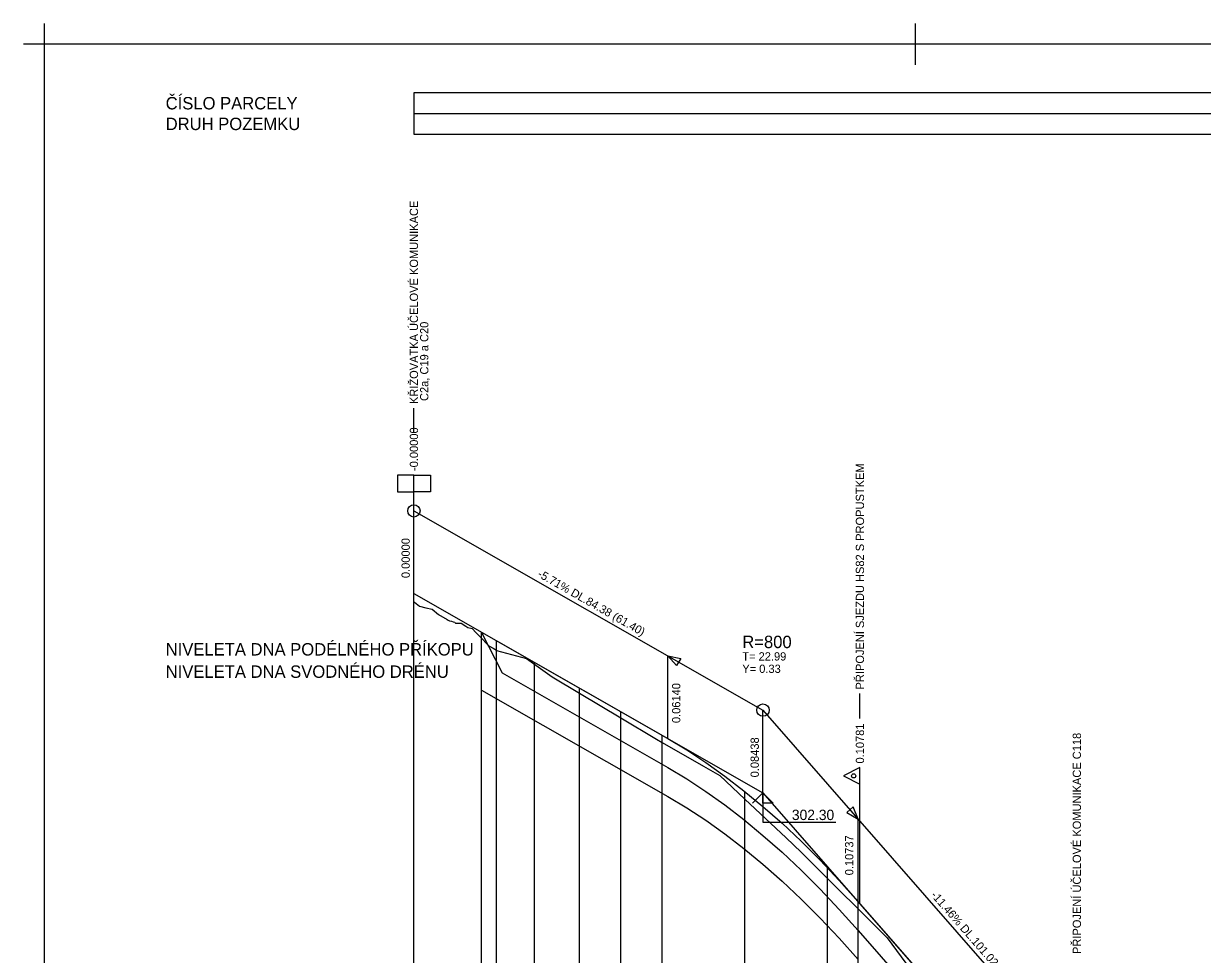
# Model space of a CAD drawing. Extents: x -24 to 1036, y -50 to 554.
# Drawn here: x -24.4 to 260.6, y 328.9 to 554 of the extents above; entities that cross this region are included whole.
import ezdxf

# ---------------------------------------------------------------- set-up
doc = ezdxf.new("R2010")
doc.units = 0
for name, color, linetype in [('KOTA', 7, 'Continuous'), ('NOVY_STAV', 7, 'Continuous'), ('NS_OBLOUK', 7, 'Continuous'), ('POPISY_NAD_TERENEM', 7, 'Continuous'), ('PRIKOPY', 7, 'Continuous'), ('REZY_PO', 7, 'Continuous'), ('SESTAVY_REZU_PO', 7, 'Continuous'), ('SVK', 7, 'Continuous'), ('SVK_STAT', 7, 'Continuous'), ('TABULKY', 7, 'Continuous'), ('ZNACKY', 7, 'Continuous')]:
    doc.layers.add(name, color=color, linetype=linetype)

msp = doc.modelspace()

# ---------------------------------------------------------------- linework, layer by layer
for p, q in [((-19.35, 554.04), (-19.35, 544.04)), ((-19.35, 554.04), (-19.35, 544.04)), ((-19.35, 554.04), (-19.35, 544.04)), ((-19.35, 554.04), (-19.35, 544.04)), ((-19.35, 554.04), (-19.35, 544.04)), ((-19.35, 554.04), (-19.35, 544.04)), ((-19.35, 554.04), (-19.35, 544.04)), ((-19.35, 554.04), (-19.35, 544.04)), ((-19.35, 554.04), (-19.35, 544.04)), ((-19.35, 554.04), (-19.35, 544.04)), ((-19.35, 554.04), (-19.35, 544.04)), ((-19.35, 554.04), (-19.35, 544.04)), ((-19.35, 554.04), (-19.35, 544.04)), ((-19.35, 554.04), (-19.35, 544.04)), ((-19.35, 554.04), (-19.35, 544.04)), ((-19.35, 554.04), (-19.35, 544.04)), ((-19.35, 554.04), (-19.35, 544.04)), ((-19.35, 554.04), (-19.35, 544.04)), ((-19.35, 554.04), (-19.35, 544.04)), ((-19.35, 554.04), (-19.35, 544.04)), ((-19.35, 554.04), (-19.35, 544.04)), ((-19.35, 554.04), (-19.35, 544.04)), ((-19.35, 554.04), (-19.35, 544.04)), ((-19.35, 554.04), (-19.35, 544.04)), ((-19.35, 554.04), (-19.35, 544.04)), ((-19.35, 554.04), (-19.35, 544.04)), ((-19.35, 554.04), (-19.35, 544.04)), ((-19.35, 554.04), (-19.35, 544.04)), ((-19.35, 554.04), (-19.35, 544.04)), ((-19.35, 554.04), (-19.35, 544.04)), ((-19.35, 554.04), (-19.35, 544.04)), ((-19.35, 554.04), (-19.35, 544.04)), ((-19.35, 554.04), (-19.35, 544.04)), ((-19.35, 554.04), (-19.35, 544.04)), ((-19.35, 554.04), (-19.35, 544.04)), ((-19.35, 554.04), (-19.35, 544.04)), ((-19.35, 554.04), (-19.35, 544.04)), ((-19.35, 554.04), (-19.35, 544.04)), ((-19.35, 554.04), (-19.35, 544.04)), ((-19.35, 554.04), (-19.35, 544.04)), ((-19.35, 554.04), (-19.35, 544.04)), ((-19.35, 554.04), (-19.35, 544.04)), ((-19.35, 554.04), (-19.35, 544.04)), ((-19.35, 554.04), (-19.35, 544.04)), ((-19.35, 554.04), (-19.35, 544.04)), ((-19.35, 554.04), (-19.35, 544.04)), ((-19.35, 554.04), (-19.35, 544.04)), ((-19.35, 554.04), (-19.35, 544.04)), ((-19.35, 554.04), (-19.35, 544.04)), ((-19.35, 554.04), (-19.35, 544.04)), ((-19.35, 554.04), (-19.35, 544.04)), ((-19.35, 554.04), (-19.35, 544.04)), ((-19.35, 554.04), (-19.35, 544.04)), ((-19.35, 554.04), (-19.35, 544.04)), ((-19.35, 554.04), (-19.35, 544.04)), ((-19.35, 554.04), (-19.35, 544.04)), ((-19.35, 554.04), (-19.35, 544.04)), ((-19.35, 554.04), (-19.35, 544.04)), ((-19.35, 554.04), (-19.35, 544.04)), ((-19.35, 554.04), (-19.35, 544.04)), ((191.15, 554.04), (191.15, 544.04)), ((191.15, 554.04), (191.15, 544.04)), ((191.15, 554.04), (191.15, 544.04)), ((191.15, 554.04), (191.15, 544.04)), ((191.15, 554.04), (191.15, 544.04)), ((191.15, 554.04), (191.15, 544.04)), ((191.15, 554.04), (191.15, 544.04)), ((191.15, 554.04), (191.15, 544.04)), ((191.15, 554.04), (191.15, 544.04)), ((191.15, 554.04), (191.15, 544.04)), ((191.15, 554.04), (191.15, 544.04)), ((191.15, 554.04), (191.15, 544.04)), ((191.15, 554.04), (191.15, 544.04)), ((191.15, 554.04), (191.15, 544.04)), ((191.15, 554.04), (191.15, 544.04)), ((191.15, 554.04), (191.15, 544.04)), ((191.15, 554.04), (191.15, 544.04)), ((191.15, 554.04), (191.15, 544.04)), ((191.15, 554.04), (191.15, 544.04)), ((191.15, 554.04), (191.15, 544.04)), ((191.15, 554.04), (191.15, 544.04)), ((191.15, 554.04), (191.15, 544.04)), ((191.15, 554.04), (191.15, 544.04)), ((191.15, 554.04), (191.15, 544.04)), ((191.15, 554.04), (191.15, 544.04)), ((191.15, 554.04), (191.15, 544.04)), ((191.15, 554.04), (191.15, 544.04)), ((191.15, 554.04), (191.15, 544.04)), ((191.15, 554.04), (191.15, 544.04)), ((191.15, 554.04), (191.15, 544.04)), ((-14.35, 549.04), (-24.35, 549.04)), ((-14.35, 549.04), (-24.35, 549.04)), ((-14.35, 549.04), (-24.35, 549.04)), ((-14.35, 549.04), (-24.35, 549.04)), ((-14.35, 549.04), (-24.35, 549.04)), ((-14.35, 549.04), (-24.35, 549.04)), ((-14.35, 549.04), (-24.35, 549.04)), ((-14.35, 549.04), (-24.35, 549.04)), ((-14.35, 549.04), (-24.35, 549.04)), ((-14.35, 549.04), (-24.35, 549.04)), ((-14.35, 549.04), (-24.35, 549.04)), ((-14.35, 549.04), (-24.35, 549.04)), ((-14.35, 549.04), (-24.35, 549.04)), ((-14.35, 549.04), (-24.35, 549.04)), ((-14.35, 549.04), (-24.35, 549.04)), ((-14.35, 549.04), (-24.35, 549.04)), ((-14.35, 549.04), (-24.35, 549.04)), ((-14.35, 549.04), (-24.35, 549.04)), ((-14.35, 549.04), (-24.35, 549.04)), ((-14.35, 549.04), (-24.35, 549.04)), ((-14.35, 549.04), (-24.35, 549.04)), ((-14.35, 549.04), (-24.35, 549.04)), ((-14.35, 549.04), (-24.35, 549.04)), ((-14.35, 549.04), (-24.35, 549.04)), ((-14.35, 549.04), (-24.35, 549.04)), ((-14.35, 549.04), (-24.35, 549.04)), ((-14.35, 549.04), (-24.35, 549.04)), ((-14.35, 549.04), (-24.35, 549.04)), ((-14.35, 549.04), (-24.35, 549.04)), ((-14.35, 549.04), (-24.35, 549.04)), ((-14.35, 549.04), (-24.35, 549.04)), ((-14.35, 549.04), (-24.35, 549.04)), ((-14.35, 549.04), (-24.35, 549.04)), ((-14.35, 549.04), (-24.35, 549.04)), ((-14.35, 549.04), (-24.35, 549.04)), ((-14.35, 549.04), (-24.35, 549.04)), ((-14.35, 549.04), (-24.35, 549.04)), ((-14.35, 549.04), (-24.35, 549.04)), ((-14.35, 549.04), (-24.35, 549.04)), ((-14.35, 549.04), (-24.35, 549.04)), ((-14.35, 549.04), (-24.35, 549.04)), ((-14.35, 549.04), (-24.35, 549.04)), ((-14.35, 549.04), (-24.35, 549.04)), ((-14.35, 549.04), (-24.35, 549.04)), ((-14.35, 549.04), (-24.35, 549.04)), ((-14.35, 549.04), (-24.35, 549.04)), ((-14.35, 549.04), (-24.35, 549.04)), ((-14.35, 549.04), (-24.35, 549.04)), ((-14.35, 549.04), (-24.35, 549.04)), ((-14.35, 549.04), (-24.35, 549.04)), ((-14.35, 549.04), (-24.35, 549.04)), ((-14.35, 549.04), (-24.35, 549.04)), ((-14.35, 549.04), (-24.35, 549.04)), ((-14.35, 549.04), (-24.35, 549.04)), ((-14.35, 549.04), (-24.35, 549.04)), ((-14.35, 549.04), (-24.35, 549.04)), ((-14.35, 549.04), (-24.35, 549.04)), ((-14.35, 549.04), (-24.35, 549.04)), ((-14.35, 549.04), (-24.35, 549.04)), ((-14.35, 549.04), (-24.35, 549.04)), ((196.15, 549.04), (186.15, 549.04)), ((196.15, 549.04), (186.15, 549.04)), ((196.15, 549.04), (186.15, 549.04)), ((196.15, 549.04), (186.15, 549.04)), ((196.15, 549.04), (186.15, 549.04)), ((196.15, 549.04), (186.15, 549.04)), ((196.15, 549.04), (186.15, 549.04)), ((196.15, 549.04), (186.15, 549.04)), ((196.15, 549.04), (186.15, 549.04)), ((196.15, 549.04), (186.15, 549.04)), ((196.15, 549.04), (186.15, 549.04)), ((196.15, 549.04), (186.15, 549.04)), ((196.15, 549.04), (186.15, 549.04)), ((196.15, 549.04), (186.15, 549.04)), ((196.15, 549.04), (186.15, 549.04)), ((196.15, 549.04), (186.15, 549.04)), ((196.15, 549.04), (186.15, 549.04)), ((196.15, 549.04), (186.15, 549.04)), ((196.15, 549.04), (186.15, 549.04)), ((196.15, 549.04), (186.15, 549.04)), ((196.15, 549.04), (186.15, 549.04)), ((196.15, 549.04), (186.15, 549.04)), ((196.15, 549.04), (186.15, 549.04)), ((196.15, 549.04), (186.15, 549.04)), ((196.15, 549.04), (186.15, 549.04)), ((196.15, 549.04), (186.15, 549.04)), ((196.15, 549.04), (186.15, 549.04)), ((196.15, 549.04), (186.15, 549.04)), ((196.15, 549.04), (186.15, 549.04)), ((196.15, 549.04), (186.15, 549.04))]:
    msp.add_line(p, q)
msp.add_lwpolyline([(1031.15, 549.04), (-19.35, 549.04), (-19.35, -44.96), (1031.15, -44.96)], close=True)
msp.add_lwpolyline([(1031.15, 549.04), (-19.35, 549.04), (-19.35, -44.96), (1031.15, -44.96)], close=True)
at = {"layer": 'KOTA'}
for points in [[(154.38, 367.96), (151.88, 365.46), (154.38, 367.96), (154.38, 360.87), (171.95, 360.87)], [(154.38, 367.96), (154.38, 367.96)], [(154.38, 367.96), (156.88, 365.46), (154.38, 365.46), (154.38, 367.96)], [(154.38, 367.96), (156.88, 365.46), (154.38, 365.46)]]:
    msp.add_lwpolyline(points, dxfattribs=at)
at = {"layer": 'NOVY_STAV'}
for points in [[(70, 416.16), (70, 436.16)], [(70, 436.16), (154.38, 387.96)], [(70, 416.16), (154.38, 367.96), (255.4, 252.21), (475.16, 150.4), (545.37, 201.67), (768.49, 157.64), (859.4, 190.25)], [(70, 416.16), (131.4, 381.09), (135.99, 378.33), (140.59, 375.31), (145.19, 372.02), (149.78, 368.47), (154.38, 364.66), (158.98, 360.58), (163.58, 356.24), (168.17, 351.63), (172.77, 346.76), (177.37, 341.62), (221.27, 291.32)], [(154.38, 367.96), (154.38, 387.96)], [(154.38, 387.96), (255.4, 272.21)]]:
    msp.add_lwpolyline(points, dxfattribs=at)
for centre in [(70, 436.16), (154.38, 387.96)]:
    msp.add_circle(centre, 1.5, dxfattribs=at)
at = {"layer": 'NS_OBLOUK'}
for points in [[(131.4, 381.09), (131.4, 401.09)], [(131.4, 401.09), (134.5, 400.47), (133.5, 398.73), (131.4, 401.09)], [(177.37, 361.62), (176.15, 364.54), (174.64, 363.22), (177.37, 361.62)], [(177.37, 341.62), (177.37, 361.62)]]:
    msp.add_lwpolyline(points, dxfattribs=at)
for points in [[(131.4, 401.09), (134.5, 400.47), (133.5, 398.73)], [(177.37, 361.62), (176.15, 364.54), (174.64, 363.22)]]:
    msp.add_lwpolyline(points, close=True, dxfattribs=at)
at = {"layer": 'POPISY_NAD_TERENEM'}
for points in [[(70, 455), (70, 461)], [(177.81, 385.95), (177.81, 391.95)]]:
    msp.add_lwpolyline(points, dxfattribs=at)
at = {"layer": 'PRIKOPY'}
for points in [[(86.3, 406.76), (91.31, 397.02), (131.4, 374.09), (135.99, 371.33), (140.59, 368.31), (145.19, 365.02), (149.78, 361.47), (154.38, 357.66), (158.98, 353.58), (163.58, 349.24), (168.17, 344.63), (172.77, 339.76), (177.37, 334.62), (221.27, 284.32)], [(86.37, 392.81), (131.4, 367.09), (135.99, 364.33), (140.59, 361.31), (145.19, 358.02), (149.78, 354.47), (154.38, 350.66), (158.98, 346.58), (163.58, 342.24), (168.17, 337.63), (172.77, 332.76), (177.37, 327.62)]]:
    msp.add_lwpolyline(points, dxfattribs=at)
at = {"layer": 'REZY_PO'}
msp.add_lwpolyline([(70, 414.16), (70.17, 414.04), (71.34, 413.12), (72.92, 412.74), (74.45, 412.36), (75.93, 411.09), (78.06, 409.89), (78.29, 409.75), (78.6, 409.57), (79.06, 409.46), (79.53, 409.35), (79.91, 409.26), (80, 409.1), (80.06, 408.99), (81.27, 408.98), (81.39, 408.98), (82.53, 408.25), (83, 407.96), (83.8, 407.77), (84.1, 407.7), (85.07, 406.69), (86.34, 405.38), (87.73, 403.95), (88.15, 403.53), (89.13, 402.92), (89.94, 402.43), (90, 402.41), (97.24, 400.43), (100, 398.45), (103.43, 395.99), (110, 392.06), (120, 386.08), (120, 386.08), (128.66, 380.91), (130, 380.14), (140, 374.42), (143.92, 372.18), (150, 366.45), (160, 357.03), (163.64, 353.6), (170, 347.26), (180, 337.29), (184.41, 332.89), (190, 325.2)], dxfattribs=at)
at = {"layer": 'SVK'}
for points in [[(90, 87), (90, 404.74)], [(110, 87), (110, 393.31)], [(130, 87), (130, 381.89)], [(150, 87), (150, 368.29)]]:
    msp.add_lwpolyline(points, dxfattribs=at)
at = {"layer": 'SVK_STAT'}
for points in [[(70, 87), (70, 416.16)], [(86.34, 87), (86.34, 406.83)], [(99.13, 87), (99.13, 399.52)], [(120, 87), (120, 387.6)], [(170, 87), (170, 349.69)], [(177.37, 87), (177.37, 341.62)]]:
    msp.add_lwpolyline(points, dxfattribs=at)
at = {"layer": 'TABULKY'}
for points in [[(70, 527.27), (859.4, 527.27), (859.4, 537.27), (70, 537.27), (70, 527.27)], [(70, 527.27), (859.4, 527.27), (859.4, 537.27), (70, 537.27), (70, 527.27)], [(70, 532.27), (859.4, 532.27)], [(70, 532.27), (859.4, 532.27)]]:
    msp.add_lwpolyline(points, dxfattribs=at)
at = {"layer": 'ZNACKY'}
for points in [[(70, 416.16), (70, 444.8), (66, 444.8), (66, 440.8), (70, 440.8)], [(70, 444.8), (74, 444.8), (74, 440.8), (70, 440.8)], [(177.81, 341.11), (177.81, 374.05), (173.81, 372.05), (177.81, 370.05)]]:
    msp.add_lwpolyline(points, dxfattribs=at)
msp.add_circle((176.31, 372.05), 0.5, dxfattribs=at)

# ---------------------------------------------------------------- texts
at = {"layer": 'KOTA'}
msp.add_text('302.30', height=2.5, dxfattribs=at).set_placement((161.37, 361.37))
at = {"layer": 'NOVY_STAV'}
for s, rotation, p in [(' 0.00000', 90, (69, 419.16)), ('-5.71% DL.84.38 (61.40)', 330.2642, (99.72, 420.34)), (' 0.08438', 90, (153.38, 370.96)), ('-11.46% DL.101.02 (43.90)', 311.111, (194.83, 343.13))]:
    msp.add_text(s, height=2, rotation=rotation, dxfattribs=at).set_placement(p)
at = {"layer": 'NS_OBLOUK'}
for s, height, p in [('R=800', 3, (149.38, 402.96)), ('T= 22.99', 2, (149.38, 399.96)), ('Y= 0.33', 2, (149.38, 396.96))]:
    msp.add_text(s, height=height, dxfattribs=at).set_placement(p)
for s, p in [(' 0.06140', (134.4, 384.09)), (' 0.10737', (176.22, 347.26))]:
    msp.add_text(s, height=2, rotation=90, dxfattribs=at).set_placement(p)
at = {"layer": 'POPISY_NAD_TERENEM'}
for s, p in [('KŘIŽOVATKA ÚČELOVÉ KOMUNIKACE                                                                 ', (71, 462)), (' C2a, C19 a C20', (73.5, 462)), ('PŘIPOJENÍ SJEZDU HS82 S PROPUSTKEM', (178.81, 392.95)), ('PŘIPOJENÍ ÚČELOVÉ KOMUNIKACE C118', (231.25, 328.97))]:
    msp.add_text(s, height=2, rotation=90, dxfattribs=at).set_placement(p)
at = {"layer": 'SESTAVY_REZU_PO'}
for s, p in [('NIVELETA DNA PODÉLNÉHO PŘÍKOPU', (10, 401.17)), ('NIVELETA DNA SVODNÉHO DRÉNU', (10, 395.77))]:
    msp.add_text(s, height=3, dxfattribs=at).set_placement(p)
at = {"layer": 'TABULKY'}
for s, p in [('ČÍSLO PARCELY', (10, 533.27)), ('ČÍSLO PARCELY', (10, 533.27)), ('DRUH POZEMKU', (10, 528.27)), ('DRUH POZEMKU', (10, 528.27))]:
    msp.add_text(s, height=3, dxfattribs=at).set_placement(p)
at = {"layer": 'ZNACKY'}
for s, p in [('-0.00000', (71, 445.8)), ('0.10781', (178.81, 375.05))]:
    msp.add_text(s, height=2, rotation=90, dxfattribs=at).set_placement(p)

doc.saveas('drawing.dxf')
